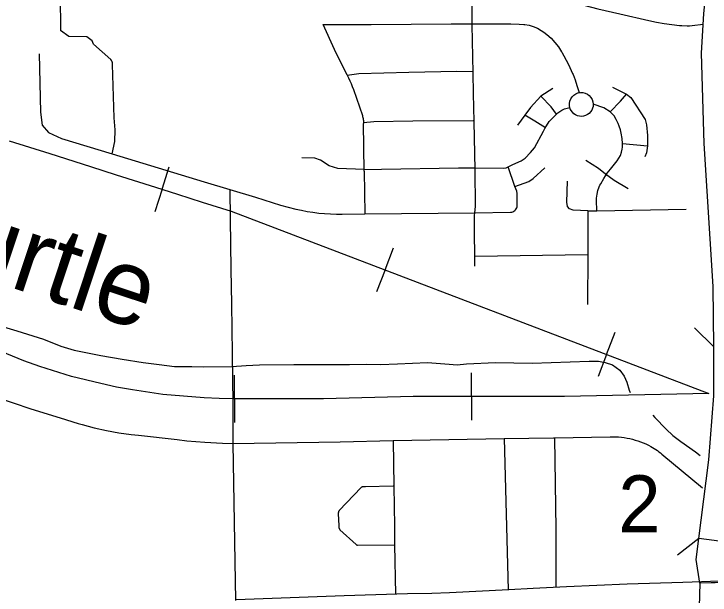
# Model space of a CAD drawing. Extents: x 309348 to 309445, y 336383 to 336484.
# Drawn here: x 309359.624 to 309361.386, y 336388.645 to 336390.116 of the extents above; entities that cross this region are included whole.
import ezdxf

# ---------------------------------------------------------------- set-up
doc = ezdxf.new("R2010")
doc.units = 0
doc.layers.add('R_Annotation', color=7, linetype='Continuous')

msp = doc.modelspace()

# ---------------------------------------------------------------- linework, layer by layer
at = {"layer": 'R_Annotation'}
for p, q in [((309359.9993, 336389.6721), (309360.0176, 336389.7293)), ((309359.9993, 336389.6721), (309359.9811, 336389.615)), ((309360.5636, 336389.4683), (309360.585, 336389.5243)), ((309360.5636, 336389.4683), (309360.5422, 336389.4122)), ((309361.1243, 336389.2541), (309361.1457, 336389.3102)), ((309361.1243, 336389.2541), (309361.1029, 336389.198)), ((309360.7827, 336389.1476), (309360.7827, 336389.2076)), ((309360.1826, 336389.1417), (309360.1825, 336389.2018)), ((309360.1826, 336389.1417), (309360.1827, 336389.0817)), ((309360.7827, 336389.1476), (309360.7827, 336389.0876)), ((309361.4931, 336388.7705), (309361.3578, 336388.7879))]:
    msp.add_line(p, q, dxfattribs=at)
for points in [[(309361.3992, 336388.6762), (309361.3605, 336388.6746), (309361.351, 336388.735), (309361.3834, 336388.9874), (309361.3954, 336389.1492), (309361.3959, 336389.2735), (309361.3938, 336389.426), (309361.371, 336389.7884), (309361.3649, 336390.0172), (309361.3706, 336390.1172), (309361.3806, 336390.2178), (309361.3934, 336390.2819), (309361.5956, 336390.981), (309361.63, 336391.0922), (309361.6642, 336391.072)], [(309359.7312, 336390.2864), (309359.732, 336390.285), (309359.7328, 336390.2837), (309359.7335, 336390.2823), (309359.7342, 336390.2809), (309359.7348, 336390.2795), (309359.7353, 336390.278), (309359.7359, 336390.2765), (309359.7363, 336390.2751), (309359.7368, 336390.2736), (309359.7371, 336390.272), (309359.7374, 336390.2705), (309359.7377, 336390.269), (309359.7379, 336390.2674), (309359.7381, 336390.2659), (309359.7412, 336390.1644), (309359.7422, 336390.0744)], [(309360.7843, 336390.0885), (309360.7839, 336390.226)], [(309361.0469, 336390.1433), (309361.1022, 336390.1294), (309361.1578, 336390.1167), (309361.2313, 336390.0994), (309361.2504, 336390.0953), (309361.2697, 336390.0919), (309361.289, 336390.0891), (309361.3085, 336390.0871), (309361.3149, 336390.0866)], [(309360.4066, 336390.0891), (309360.5288, 336390.0894), (309360.7313, 336390.0911), (309360.7843, 336390.0911)], [(309360.4678, 336389.9609), (309360.4355, 336390.0265), (309360.4066, 336390.0891)], [(309360.7843, 336390.0911), (309360.8784, 336390.0913), (309360.8816, 336390.0913), (309360.9029, 336390.0905), (309360.915, 336390.0895), (309360.917, 336390.0893), (309360.928, 336390.0874), (309360.9388, 336390.0842), (309360.9492, 336390.0799), (309360.9591, 336390.0745), (309360.9653, 336390.0703), (309360.973, 336390.0643), (309360.9838, 336390.0546), (309360.9936, 336390.044), (309361.0026, 336390.0326), (309361.0105, 336390.0205), (309361.0113, 336390.0191), (309361.0164, 336390.0101), (309361.028, 336389.988), (309361.0384, 336389.9655), (309361.0397, 336389.9625), (309361.0447, 336389.9495), (309361.0493, 336389.9346), (309361.0547, 336389.9172)], [(309360.7867, 336389.9671), (309360.7843, 336390.0885)], [(309361.3149, 336390.0866), (309361.328, 336390.0857), (309361.3344, 336390.0861), (309361.3409, 336390.0867), (309361.3691, 336390.0903)], [(309359.8726, 336389.7622), (309359.8799, 336389.7935), (309359.8801, 336389.8229), (309359.8782, 336389.8533), (309359.8741, 336389.9882), (309359.8741, 336389.9889), (309359.874, 336389.9896), (309359.874, 336389.9903), (309359.8739, 336389.991), (309359.8737, 336389.9917), (309359.8736, 336389.9923), (309359.8734, 336389.993), (309359.8732, 336389.9937), (309359.873, 336389.9943), (309359.8728, 336389.995), (309359.8725, 336389.9956), (309359.8722, 336389.9962), (309359.8719, 336389.9969), (309359.8716, 336389.9975), (309359.8713, 336389.9981), (309359.8709, 336389.9987), (309359.8705, 336389.9992), (309359.8701, 336389.9998), (309359.8697, 336390.0003), (309359.8693, 336390.0009), (309359.8257, 336390.0395), (309359.8226, 336390.0479), (309359.8084, 336390.0583), (309359.7636, 336390.059), (309359.7422, 336390.0744)], [(309359.6883, 336390.0149), (309359.6912, 336389.8678), (309359.6959, 336389.8348), (309359.7121, 336389.8156), (309359.7445, 336389.8006), (309359.8726, 336389.7622), (309360.1059, 336389.6911), (309360.1707, 336389.6718)], [(309360.4678, 336389.9609), (309360.4974, 336389.9654), (309360.6238, 336389.9687), (309360.7454, 336389.9712), (309360.7867, 336389.9704)], [(309360.4678, 336389.9609), (309360.4714, 336389.954), (309360.4747, 336389.9469), (309360.4779, 336389.9398), (309360.4807, 336389.9326), (309360.4834, 336389.9252), (309360.5061, 336389.8594), (309360.5068, 336389.8569), (309360.5074, 336389.8543), (309360.5079, 336389.8518), (309360.5083, 336389.8492), (309360.5087, 336389.8466), (309360.5089, 336389.844), (309360.5091, 336389.8414), (309360.5092, 336389.8388), (309360.5092, 336389.8385)], [(309360.7889, 336389.8435), (309360.7878, 336389.9143), (309360.7867, 336389.9671)], [(309360.9886, 336389.9276), (309360.9576, 336389.9083), (309360.9317, 336389.8795), (309360.9173, 336389.8596), (309360.8985, 336389.8342)], [(309361.139, 336389.9309), (309361.1744, 336389.9132), (309361.1854, 336389.9049), (309361.2219, 336389.8491), (309361.2252, 336389.8353), (309361.228, 336389.8087), (309361.2275, 336389.7822), (309361.2252, 336389.7645), (309361.2208, 336389.7545)], [(309360.9979, 336389.8624), (309360.9836, 336389.8806), (309360.9576, 336389.9083)], [(309361.0313, 336389.8789), (309361.0304, 336389.8834), (309361.0303, 336389.8895), (309361.0314, 336389.8955), (309361.0337, 336389.9012), (309361.037, 336389.9063), (309361.0414, 336389.9106), (309361.0465, 336389.9139), (309361.0519, 336389.9161)], [(309361.0519, 336389.9161), (309361.0521, 336389.9161), (309361.0581, 336389.9172), (309361.0642, 336389.917), (309361.0702, 336389.9156), (309361.0757, 336389.913), (309361.0806, 336389.9094), (309361.0846, 336389.9048), (309361.0877, 336389.8995), (309361.0897, 336389.8938), (309361.0904, 336389.8877), (309361.0899, 336389.8816), (309361.0899, 336389.8816)], [(309361.1335, 336389.8679), (309361.1594, 336389.8955), (309361.1744, 336389.9132)], [(309360.7916, 336389.7265), (309360.8642, 336389.7258), (309360.8697, 336389.7263), (309360.8874, 336389.7346), (309360.9084, 336389.7446), (309360.9178, 336389.7512), (309360.9317, 336389.7656), (309360.9416, 336389.7772), (309360.9648, 336389.8192), (309360.9681, 336389.8259), (309360.9792, 336389.8436), (309360.9903, 336389.8552), (309361.0013, 336389.8657), (309361.0107, 336389.8729), (309361.0179, 336389.8762), (309361.0313, 336389.8789)], [(309361.0899, 336389.8816), (309361.0888, 336389.8773), (309361.0867, 336389.8725), (309361.0837, 336389.8682), (309361.0801, 336389.8644), (309361.0759, 336389.8613), (309361.0712, 336389.8589), (309361.0661, 336389.8575), (309361.0609, 336389.8569), (309361.0557, 336389.8573), (309361.0506, 336389.8585), (309361.0458, 336389.8606), (309361.0414, 336389.8636), (309361.0376, 336389.8672), (309361.0345, 336389.8715), (309361.0322, 336389.8762), (309361.0313, 336389.8789)], [(309361.0995, 336389.6179), (309361.099, 336389.645), (309361.099, 336389.6499), (309361.1001, 336389.6598), (309361.1023, 336389.6695), (309361.1057, 336389.6788), (309361.1075, 336389.6827), (309361.1093, 336389.6863), (309361.1171, 336389.6998), (309361.1259, 336389.7127), (309361.1339, 336389.7228), (309361.1513, 336389.7446), (309361.1556, 336389.7506), (309361.1595, 336389.7581), (309361.1622, 336389.766), (309361.1639, 336389.7742), (309361.1642, 336389.7787), (309361.1643, 336389.7881), (309361.1635, 336389.8012), (309361.1614, 336389.8141), (309361.1593, 336389.8229), (309361.1562, 336389.8319), (309361.1536, 336389.8389), (309361.1484, 336389.8491), (309361.1433, 336389.8582), (309361.1335, 336389.8679), (309361.1174, 336389.8787), (309361.0904, 336389.8877)], [(309360.9696, 336389.8282), (309360.9427, 336389.8447), (309360.9173, 336389.8596)], [(309360.5091, 336389.8414), (309360.5354, 336389.8438), (309360.6338, 336389.8455), (309360.7867, 336389.8463)], [(309360.511, 336389.7183), (309360.5092, 336389.8385)], [(309360.7917, 336389.7218), (309360.7889, 336389.8435)], [(309359.6124, 336389.7951), (309359.7154, 336389.7625), (309359.818, 336389.7296), (309359.8829, 336389.7088), (309359.9826, 336389.6775), (309360.038, 336389.6598), (309360.1008, 336389.6392), (309360.1739, 336389.6171), (309361.3829, 336389.1553)], [(309359.6124, 336389.7951), (309359.7154, 336389.7625), (309359.818, 336389.7296), (309359.8829, 336389.7088), (309359.9826, 336389.6775), (309360.038, 336389.6598), (309360.1008, 336389.6392), (309360.1739, 336389.6171), (309361.3829, 336389.1553)], [(309361.1643, 336389.7881), (309361.2275, 336389.7822)], [(309360.5109, 336389.7223), (309360.4444, 336389.7248), (309360.4221, 336389.7314), (309360.3998, 336389.7463), (309360.3858, 336389.7512), (309360.3527, 336389.7521)], [(309361.1793, 336389.6732), (309361.1434, 336389.6943), (309361.1218, 336389.7109), (309361.1036, 336389.7252), (309361.0721, 336389.7451)], [(309360.5109, 336389.7223), (309360.5544, 336389.7231), (309360.7495, 336389.7264), (309360.7916, 336389.7265)], [(309360.511, 336389.7183), (309360.5128, 336389.6099)], [(309360.791, 336389.6127), (309360.8812, 336389.6141), (309360.8815, 336389.6141), (309360.8844, 336389.6144), (309360.8871, 336389.6152), (309360.8897, 336389.6165), (309360.8921, 336389.6182), (309360.8941, 336389.6203), (309360.8957, 336389.6227), (309360.8969, 336389.6253), (309360.8976, 336389.6282), (309360.8978, 336389.6311), (309360.8977, 336389.6323), (309360.8977, 336389.6605), (309360.8977, 336389.6612), (309360.897, 336389.6675), (309360.895, 336389.6736), (309360.8919, 336389.6792), (309360.8917, 336389.6794), (309360.8754, 336389.729)], [(309360.791, 336389.6127), (309360.7926, 336389.6288), (309360.7917, 336389.7218)], [(309360.8919, 336389.6792), (309360.9272, 336389.6921), (309360.9383, 336389.6992), (309360.9676, 336389.7269)], [(309361.0767, 336389.6175), (309361.0395, 336389.6191), (309361.0301, 336389.6224), (309361.0251, 336389.629), (309361.024, 336389.6395), (309361.0251, 336389.6926)], [(309360.1707, 336389.6718), (309360.2356, 336389.6524), (309360.2993, 336389.6324), (309360.3375, 336389.6223), (309360.352, 336389.6191), (309360.3665, 336389.6163), (309360.3812, 336389.6139), (309360.3959, 336389.612), (309360.4107, 336389.6106), (309360.4255, 336389.6097), (309360.4403, 336389.6092), (309360.4552, 336389.6092), (309360.5128, 336389.6099)], [(309360.1707, 336389.6718), (309360.1716, 336389.5967), (309360.1736, 336389.4698), (309360.1749, 336389.3814), (309360.1767, 336389.2565), (309360.1784, 336389.1296), (309360.1787, 336389.0282)], [(309360.5128, 336389.6099), (309360.791, 336389.6127)], [(309360.7902, 336389.5629), (309360.7898, 336389.6057), (309360.791, 336389.6127)], [(309361.0767, 336389.6175), (309361.0995, 336389.6179)], [(309361.0767, 336389.6175), (309361.0769, 336389.5687)], [(309361.0995, 336389.6179), (309361.3258, 336389.6223)], [(309360.7908, 336389.5029), (309360.7902, 336389.5629)], [(309361.0769, 336389.5687), (309361.0771, 336389.5343), (309361.0769, 336389.5075)], [(309360.7908, 336389.5029), (309361.0769, 336389.5075)], [(309360.791, 336389.4778), (309360.7908, 336389.5029)], [(309361.0769, 336389.5075), (309361.0763, 336389.3809)], [(309359.5604, 336389.335), (309359.6315, 336389.3135), (309359.6989, 336389.2926), (309359.7432, 336389.2751), (309359.7765, 336389.2648), (309359.8442, 336389.2515), (309359.8983, 336389.242), (309359.9511, 336389.2334), (309359.9922, 336389.2284), (309360.0309, 336389.2237), (309360.0744, 336389.2237), (309360.1047, 336389.2228), (309360.1762, 336389.2232), (309360.2117, 336389.2264), (309360.2462, 336389.2274), (309360.3331, 336389.2288), (309360.474, 336389.2288), (309360.5161, 336389.2293), (309360.5523, 336389.2284), (309360.595, 336389.2301), (309360.671, 336389.2335), (309360.726, 336389.2296), (309360.7459, 336389.228), (309360.7698, 336389.2301), (309360.8433, 336389.2334), (309360.9362, 336389.2316), (309361.0798, 336389.2371), (309361.1036, 336389.2371), (309361.1207, 336389.2338), (309361.139, 336389.2277), (309361.1578, 336389.214), (309361.1688, 336389.1988), (309361.1752, 336389.1842), (309361.1814, 336389.1636), (309361.1838, 336389.1576)], [(309361.347, 336389.3211), (309361.3959, 336389.2735)], [(309361.3829, 336389.1553), (309361.0178, 336389.1476), (309360.635, 336389.1476), (309360.4079, 336389.1421), (309360.1803, 336389.1417), (309360.144, 336389.1429), (309360.1056, 336389.1445), (309360.0537, 336389.1482), (309360.001, 336389.1528), (309359.9245, 336389.1647), (309359.8836, 336389.1716), (309359.8439, 336389.1801), (309359.7699, 336389.1981), (309359.6899, 336389.2234), (309359.649, 336389.2376), (309359.5768, 336389.2675)], [(309360.1803, 336389.1417), (309360.144, 336389.1429), (309360.1056, 336389.1445), (309360.0537, 336389.1482), (309360.001, 336389.1528), (309359.9245, 336389.1647), (309359.8836, 336389.1716), (309359.8439, 336389.1801), (309359.7699, 336389.1981), (309359.6899, 336389.2234), (309359.649, 336389.2376), (309359.5768, 336389.2675)], [(309359.5057, 336389.1725), (309359.5423, 336389.1579), (309359.622, 336389.1313), (309359.6672, 336389.1165), (309359.741, 336389.0932), (309359.7865, 336389.0795), (309359.7966, 336389.0766), (309359.8272, 336389.0686), (309359.8582, 336389.0617), (309359.8894, 336389.056), (309359.9208, 336389.0516), (309359.9398, 336389.0494), (309360.0372, 336389.0384), (309360.062, 336389.0357), (309360.1071, 336389.0319), (309360.1523, 336389.0292), (309360.1787, 336389.0282)], [(309361.3829, 336389.1553), (309361.0178, 336389.1476), (309360.635, 336389.1476), (309360.4079, 336389.1421), (309360.1803, 336389.1417)], [(309361.2416, 336389.1002), (309361.2466, 336389.0941), (309361.2747, 336389.065), (309361.2923, 336389.0489), (309361.3126, 336389.0336), (309361.349, 336389.0078), (309361.3612, 336388.998)], [(309360.9926, 336389.043), (309361.1334, 336389.0459), (309361.1405, 336389.0459), (309361.1477, 336389.0457), (309361.1548, 336389.0452), (309361.1619, 336389.0445), (309361.169, 336389.0436), (309361.176, 336389.0424), (309361.183, 336389.041), (309361.1899, 336389.0393), (309361.1968, 336389.0374), (309361.2036, 336389.0352), (309361.2103, 336389.0328), (309361.217, 336389.0302), (309361.2235, 336389.0274), (309361.23, 336389.0243), (309361.2363, 336389.0211), (309361.2406, 336389.0187), (309361.2447, 336389.0162), (309361.2488, 336389.0135), (309361.2528, 336389.0107), (309361.2567, 336389.0078), (309361.2605, 336389.0047), (309361.2642, 336389.0016), (309361.3667, 336388.9161)], [(309360.1787, 336389.0282), (309360.4502, 336389.0332), (309360.5838, 336389.036)], [(309360.1787, 336389.0282), (309360.1836, 336388.7297)], [(309360.5838, 336389.036), (309360.7247, 336389.0389), (309360.8651, 336389.041)], [(309360.5838, 336389.036), (309360.5856, 336388.9204), (309360.5872, 336388.8189)], [(309360.8651, 336389.041), (309360.9901, 336389.0429), (309360.9926, 336389.043)], [(309360.8651, 336389.041), (309360.8752, 336388.6582)], [(309360.9926, 336389.043), (309360.9959, 336388.8118)], [(309360.5856, 336388.9204), (309360.5845, 336388.9204), (309360.5137, 336388.9192), (309360.5086, 336388.9191), (309360.5083, 336388.9191), (309360.508, 336388.9191), (309360.5077, 336388.919), (309360.5073, 336388.919), (309360.507, 336388.9189), (309360.5067, 336388.9189), (309360.5064, 336388.9188), (309360.5061, 336388.9187), (309360.5058, 336388.9186), (309360.5055, 336388.9185), (309360.5052, 336388.9184), (309360.505, 336388.9183), (309360.5049, 336388.9182), (309360.5047, 336388.9182), (309360.5045, 336388.9181), (309360.5043, 336388.918), (309360.5042, 336388.9178), (309360.504, 336388.9177), (309360.5038, 336388.9176), (309360.5037, 336388.9175), (309360.5035, 336388.9174), (309360.5034, 336388.9172), (309360.5032, 336388.9171), (309360.5031, 336388.9169), (309360.4477, 336388.8591), (309360.4475, 336388.8589), (309360.4473, 336388.8587), (309360.4472, 336388.8584), (309360.447, 336388.8582), (309360.4468, 336388.858), (309360.4466, 336388.8577), (309360.4465, 336388.8575), (309360.4464, 336388.8572), (309360.4462, 336388.857), (309360.4461, 336388.8567), (309360.446, 336388.8564), (309360.4459, 336388.8561), (309360.4458, 336388.8559), (309360.4457, 336388.8556), (309360.4456, 336388.8553), (309360.4456, 336388.855), (309360.4455, 336388.8547), (309360.4455, 336388.8544), (309360.4454, 336388.8541), (309360.4453, 336388.853), (309360.4451, 336388.8519), (309360.4449, 336388.8508), (309360.4462, 336388.8207), (309360.4462, 336388.8199), (309360.4463, 336388.819), (309360.4464, 336388.8182), (309360.4465, 336388.8173), (309360.4467, 336388.8165), (309360.4468, 336388.8157), (309360.447, 336388.8148), (309360.4473, 336388.814), (309360.4474, 336388.8138), (309360.4474, 336388.8135), (309360.4475, 336388.8133), (309360.4477, 336388.813), (309360.4478, 336388.8128), (309360.4479, 336388.8125), (309360.448, 336388.8123), (309360.4482, 336388.8121), (309360.4483, 336388.8118), (309360.4485, 336388.8116), (309360.4486, 336388.8114), (309360.4488, 336388.8112), (309360.449, 336388.811), (309360.4491, 336388.8108), (309360.4493, 336388.8106), (309360.4495, 336388.8104), (309360.4907, 336388.7728), (309360.4909, 336388.7727), (309360.4911, 336388.7725), (309360.4913, 336388.7724), (309360.4915, 336388.7722), (309360.4917, 336388.7721), (309360.4919, 336388.772), (309360.4921, 336388.7718), (309360.4923, 336388.7717), (309360.4925, 336388.7716), (309360.4928, 336388.7715), (309360.493, 336388.7714), (309360.4932, 336388.7713), (309360.4934, 336388.7713), (309360.4937, 336388.7712), (309360.4939, 336388.7711), (309360.4941, 336388.7711), (309360.5869, 336388.7724), (309360.5879, 336388.7724)], [(309360.5872, 336388.8189), (309360.5879, 336388.7724), (309360.5899, 336388.6471)], [(309360.9959, 336388.8118), (309360.9962, 336388.6644)], [(309361.3578, 336388.7879), (309361.3038, 336388.7462)], [(309360.1836, 336388.7297), (309360.1852, 336388.6311)], [(309361.4105, 336388.6799), (309361.3172, 336388.6769), (309361.1765, 336388.6728), (309361.023, 336388.6655), (309360.9387, 336388.6619), (309360.8767, 336388.6583), (309360.7266, 336388.6504), (309360.6818, 336388.649), (309360.6207, 336388.648), (309360.46, 336388.6433), (309360.187, 336388.633)], [(309361.4743, 336388.6772), (309361.4175, 336388.677), (309361.3605, 336388.6746), (309361.3523, 336388.403), (309361.3596, 336388.1531), (309361.3623, 336387.9937)]]:
    msp.add_lwpolyline(points, dxfattribs=at)

# ---------------------------------------------------------------- texts
msp.add_text('Turtle', height=0.19206, rotation=341.6048, dxfattribs=at).set_placement((309359.3248, 336389.5206))
msp.add_text('2', height=0.144, dxfattribs=at).set_placement((309361.154, 336388.804))

doc.saveas('drawing.dxf')
